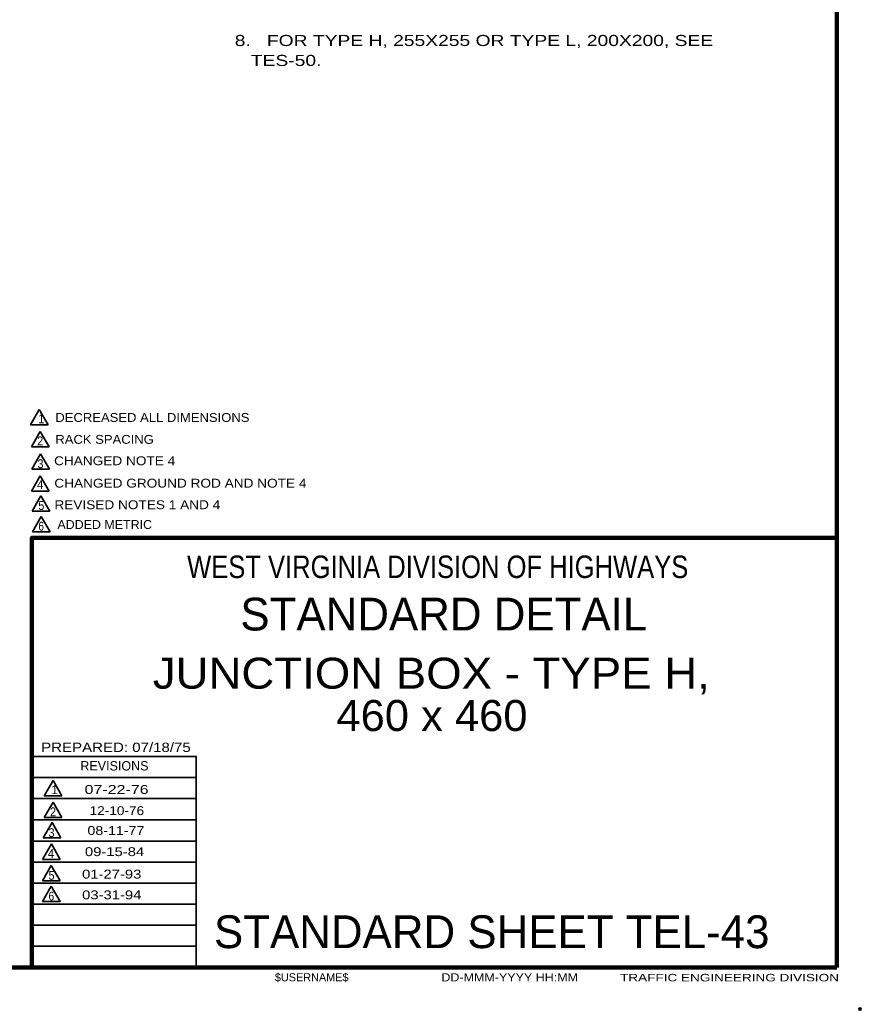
# Model space of a CAD drawing. Extents: x 918 to 1774, y -8 to 536.
# Drawn here: x 1545.7 to 1773.6, y -7.9 to 260.3 of the extents above; entities that cross this region are included whole.
import ezdxf
from ezdxf.enums import TextEntityAlignment as Align

# ---------------------------------------------------------------- set-up
doc = ezdxf.new("R2010")
doc.units = 0
doc.header["$LTSCALE"] = 1.2
doc.header["$PDMODE"] = 32
doc.header["$PDSIZE"] = 0.6
doc.layers.add('1', color=7, linetype='Continuous', lineweight=35)
doc.layers.add('61', color=7, linetype='Continuous', lineweight=35)

msp = doc.modelspace()

# ---------------------------------------------------------------- linework, layer by layer
at = {"layer": '1', "lineweight": 158}
for q in [(1766.999, 529.818), (1766.999, 120.018), (975.399, 3.718)]:
    msp.add_line((1766.999, 3.718), q, dxfattribs=at)
at = {"layer": '1', "lineweight": 13}
msp.add_line((1766.999, 3.718), (1766.999, 529.818), dxfattribs=at)
at = {"layer": '1'}
for p, q in [((1550.972, 154.767), (1548.572, 150.61)), ((1550.972, 154.767), (1553.372, 150.61)), ((1553.372, 150.61), (1548.572, 150.61)), ((1551.242, 148.832), (1548.842, 144.675)), ((1551.242, 148.832), (1553.642, 144.675)), ((1553.642, 144.675), (1548.842, 144.675)), ((1551.352, 142.785), (1548.952, 138.628)), ((1551.352, 142.785), (1553.752, 138.628)), ((1551.257, 136.802), (1548.857, 132.645)), ((1553.752, 138.628), (1548.952, 138.628)), ((1551.257, 136.802), (1553.657, 132.645)), ((1553.657, 132.645), (1548.857, 132.645)), ((1551.442, 131.357), (1549.042, 127.2)), ((1551.442, 131.357), (1553.841, 127.2)), ((1553.841, 127.2), (1549.042, 127.2)), ((1551.526, 125.785), (1549.126, 121.628)), ((1551.526, 125.785), (1553.926, 121.628)), ((1553.926, 121.628), (1549.126, 121.628)), ((1593.499, 55.118), (1548.999, 55.118)), ((1554.711, 54.267), (1552.311, 50.11)), ((1554.711, 54.267), (1557.111, 50.11)), ((1593.499, 49.418), (1548.999, 49.418)), ((1557.111, 50.11), (1552.311, 50.11)), ((1554.711, 48.458), (1552.311, 44.301)), ((1554.711, 48.458), (1557.111, 44.301)), ((1593.499, 43.618), (1548.999, 43.618)), ((1554.436, 42.924), (1552.036, 38.767)), ((1557.111, 44.301), (1552.311, 44.301)), ((1554.436, 42.924), (1556.836, 38.767)), ((1593.499, 37.918), (1548.999, 37.918)), ((1556.836, 38.767), (1552.036, 38.767)), ((1554.276, 37.116), (1551.876, 32.959)), ((1554.276, 37.116), (1556.676, 32.959)), ((1593.499, 32.218), (1548.999, 32.218)), ((1556.676, 32.959), (1551.876, 32.959)), ((1554.226, 31.288), (1551.826, 27.131)), ((1554.226, 31.288), (1556.626, 27.131)), ((1556.626, 27.131), (1551.826, 27.131)), ((1593.499, 26.518), (1548.999, 26.518)), ((1554.228, 25.662), (1551.828, 21.505)), ((1593.499, 20.818), (1548.999, 20.818)), ((1593.499, 15.118), (1548.999, 15.118)), ((1593.499, 9.418), (1548.999, 9.418))]:
    msp.add_line(p, q, dxfattribs=at)
at = {"layer": '1', "lineweight": 158}
msp.add_lwpolyline([(1548.999, 3.718), (1548.999, 120.018), (1766.999, 120.018)], dxfattribs=at)
at = {"layer": '1'}
for points in [[(1593.499, 3.718), (1593.499, 60.818), (1548.999, 60.818)], [(1554.228, 25.662), (1556.628, 21.505), (1551.828, 21.505)]]:
    msp.add_lwpolyline(points, dxfattribs=at)
msp.add_point((1773.299, -7.582), dxfattribs=at)
at = {"layer": '61', "lineweight": 53}
for q in [(1614.299, 3.718), (1614.299, 3.718), (1614.299, 3.718), (1614.599, 3.718), (1614.599, 3.718)]:
    msp.add_line((1766.999, 3.718), q, dxfattribs=at)

# ---------------------------------------------------------------- texts
at = {"layer": '1'}
for s, height, width, p in [('8.   FOR TYPE H, 255X255 OR TYPE L, 200X200, SEE', 3, 1.3, (1603.931, 253.155)), ('   TES-50.', 3, 1.3, (1603.931, 247.755)), ('DECREASED ALL DIMENSIONS', 2.4, 1.1, (1555.339, 151.391)), ('2', 2.4, 0.9, (1550.445, 145.047)), ('RACK SPACING', 2.4, 1.1, (1555.339, 145.461)), ('3', 2.4, 0.9, (1550.514, 138.841)), ('CHANGED NOTE 4', 2.4, 1.15, (1554.995, 139.668)), ('4', 2.4, 0.95, (1550.376, 133.186)), ('CHANGED GROUND ROD AND NOTE 4', 2.4, 1.15, (1555.063, 133.6)), ('5', 2.4, 0.9, (1550.745, 127.557)), ('REVISED NOTES 1 AND 4', 2.4, 1.15, (1555.087, 127.762)), ('6', 2.4, 0.85, (1550.744, 121.972)), ('ADDED METRIC', 2.4, 1.05, (1555.893, 122.409)), ('PREPARED: 07/18/75', 2.537, 1.2, (1551.499, 62.018)), ('2', 2.4, 0.9, (1553.92, 44.615)), ('3', 2.4, 0.9, (1553.508, 38.983)), ('4', 2.4, 0.95, (1553.325, 33.351)), ('5', 2.4, 0.9, (1553.496, 27.435)), ('6', 2.4, 0.85, (1553.498, 21.809)), ('DD-MMM-YYYY HH:MM', 2.2, 1.15, (1659.899, -0.082)), ('TRAFFIC ENGINEERING DIVISION', 2.031, 1.35, (1708.299, -0.082))]:
    msp.add_text(s, height=height, dxfattribs=dict(at, width=width)).set_placement(p)
for s, height, p in [('1', 2.4, (1550.652, 151.047)), ('REVISIONS', 2.537, (1562.099, 57.018)), ('1', 2.4, (1554.24, 50.613)), ('STANDARD SHEET TEL-43', 8.881, (1598.299, 8.918)), ('$USERNAME$', 2.2, (1614.799, -0.082))]:
    msp.add_text(s, height=height, dxfattribs=at).set_placement(p)
for s, height, width, p in [('WEST VIRGINIA DIVISION OF HIGHWAYS', 6.089, 0.85, (1658.899, 109.118)), ('JUNCTION BOX - TYPE H,', 8.391, 1.1, (1657.161, 79.162)), ('460 x 460', 8.391, 1.05, (1657.342, 67.706)), ('07-22-76', 2.4, 1.35, (1571.926, 50.681)), ('12-10-76', 2.4, 1.15, (1571.994, 44.943)), ('08-11-77', 2.4, 1.2, (1571.743, 39.572)), ('09-15-84', 2.4, 1.25, (1571.377, 33.834)), ('01-27-93', 2.4, 1.25, (1570.605, 27.765)), ('03-31-94', 2.4, 1.25, (1570.616, 22.139))]:
    msp.add_text(s, height=height, dxfattribs=dict(at, width=width)).set_placement(p, align=Align.CENTER)
msp.add_text('STANDARD DETAIL', height=8.881, dxfattribs=at).set_placement((1660.549, 94.918), align=Align.CENTER)

doc.saveas('drawing.dxf')
